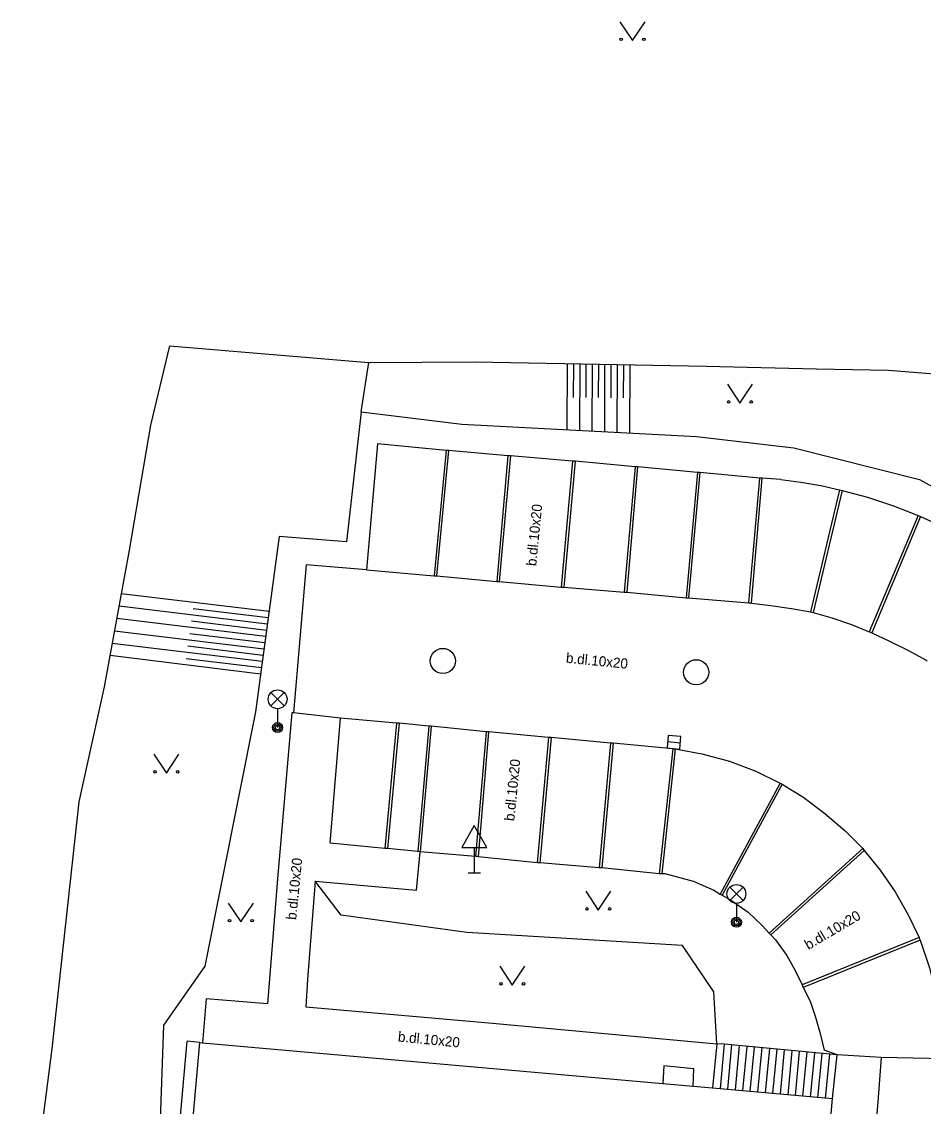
# Model space of a CAD drawing. Extents: x -598233 to -596890, y -1157848 to -1156431.
# Drawn here: x -598000.23 to -597964.39, y -1156908.64 to -1156865.51 of the extents above; entities that cross this region are included whole.
import ezdxf

# ---------------------------------------------------------------- set-up
doc = ezdxf.new("R2010")
doc.units = 0
for name, color, linetype in [('Level 10', 7, 'Continuous'), ('Level 11', 7, 'Continuous'), ('Level 14', 7, 'Continuous'), ('Level 15', 7, 'Continuous'), ('Level 25', 7, 'Continuous'), ('Level 27', 7, 'Continuous'), ('Level 33', 7, 'Continuous'), ('Level 34', 7, 'Continuous'), ('Level 36', 7, 'Continuous'), ('Level 40', 7, 'Continuous'), ('Level 5', 7, 'Continuous')]:
    doc.layers.add(name, color=color, linetype=linetype)

msp = doc.modelspace()

# ---------------------------------------------------------------- linework, layer by layer
at = {"layer": 'Level 10'}
for points in [[(-597970.06, -1156883.72), (-597970.79, -1156883.66), (-597970.84, -1156883.66), (-597970.89, -1156883.66), (-597973.27, -1156883.44), (-597973.32, -1156883.44), (-597973.37, -1156883.44), (-597975.75, -1156883.21), (-597975.8, -1156883.21), (-597975.85, -1156883.21), (-597978.23, -1156882.99), (-597978.28, -1156882.99), (-597978.33, -1156882.99), (-597980.8, -1156882.77), (-597980.85, -1156882.77), (-597980.9, -1156882.77), (-597983.26, -1156882.56), (-597983.31, -1156882.56), (-597983.36, -1156882.56), (-597986.09, -1156882.3), (-597986.53, -1156887.31), (-597988.92, -1156887.11), (-597989.43, -1156892.99)], [(-597970.06, -1156883.72), (-597969.26, -1156883.82), (-597968.46, -1156883.96), (-597967.72, -1156884.13), (-597967.67, -1156884.14)], [(-597967.67, -1156884.14), (-597967.62, -1156884.15), (-597966.61, -1156884.42), (-597965.57, -1156884.76), (-597964.6, -1156885.14), (-597964.55, -1156885.16)], [(-597964.55, -1156885.16), (-597964.5, -1156885.18), (-597963.53, -1156885.62), (-597962.54, -1156886.14), (-597961.61, -1156886.68), (-597961.57, -1156886.7)], [(-597987.97, -1156898.18), (-597987.56, -1156893.2)], [(-597985.74, -1156898.39), (-597985.79, -1156898.39), (-597987.97, -1156898.18)], [(-597984.39, -1156898.52), (-597984.49, -1156898.51), (-597985.69, -1156898.39), (-597985.74, -1156898.39)], [(-597982.14, -1156898.71), (-597982.19, -1156898.71), (-597984.39, -1156898.52)], [(-597979.69, -1156898.96), (-597979.74, -1156898.96), (-597982.09, -1156898.72), (-597982.14, -1156898.71)], [(-597977.22, -1156899.16), (-597977.27, -1156899.16), (-597979.64, -1156898.96), (-597979.69, -1156898.96)], [(-597974.84, -1156899.39), (-597974.89, -1156899.39), (-597977.17, -1156899.16), (-597977.22, -1156899.16)], [(-597974.65, -1156899.39), (-597974.79, -1156899.39), (-597974.84, -1156899.39)], [(-597973.47, -1156899.72), (-597974.65, -1156899.39)], [(-597973.47, -1156899.72), (-597972.72, -1156900.05), (-597972.46, -1156900.2), (-597972.38, -1156900.25), (-597972.01, -1156900.45), (-597971.35, -1156900.92)], [(-597971.35, -1156900.92), (-597970.79, -1156901.45), (-597970.52, -1156901.75), (-597970.45, -1156901.82), (-597970.27, -1156902.02), (-597969.81, -1156902.64)], [(-597969.81, -1156902.64), (-597969.49, -1156903.24), (-597969.21, -1156903.81), (-597969.19, -1156903.85), (-597969.16, -1156903.91), (-597968.89, -1156904.46)], [(-597968.89, -1156904.46), (-597968.67, -1156905.1), (-597968.49, -1156905.75), (-597968.33, -1156906.41)], [(-597967.82, -1156906.59), (-597968.33, -1156906.41)], [(-597963.52, -1156906.75), (-597966.06, -1156906.7), (-597967.82, -1156906.59)]]:
    msp.add_lwpolyline(points, dxfattribs=at)
at = {"layer": 'Level 11'}
for points in [[(-597983.36, -1156882.56), (-597983.84, -1156887.55)], [(-597983.26, -1156882.56), (-597983.74, -1156887.55)], [(-597980.9, -1156882.77), (-597981.35, -1156887.77)], [(-597980.8, -1156882.77), (-597981.25, -1156887.77)], [(-597978.33, -1156882.99), (-597978.78, -1156887.99)], [(-597978.23, -1156882.99), (-597978.68, -1156887.99)], [(-597975.85, -1156883.21), (-597976.28, -1156888.2)], [(-597975.75, -1156883.21), (-597976.18, -1156888.2)], [(-597973.37, -1156883.44), (-597973.82, -1156888.42)], [(-597973.27, -1156883.44), (-597973.72, -1156888.42)], [(-597971.32, -1156888.62), (-597970.89, -1156883.66)], [(-597971.22, -1156888.63), (-597970.79, -1156883.66)], [(-597967.72, -1156884.13), (-597968.87, -1156888.98)], [(-597967.62, -1156884.15), (-597968.77, -1156889)], [(-597964.6, -1156885.14), (-597966.54, -1156889.77)], [(-597964.5, -1156885.18), (-597966.44, -1156889.81)], [(-597986.53, -1156887.31), (-597983.84, -1156887.55), (-597983.79, -1156887.55), (-597983.74, -1156887.55), (-597981.35, -1156887.77), (-597981.3, -1156887.77), (-597981.25, -1156887.77), (-597978.78, -1156887.99), (-597978.73, -1156887.99), (-597978.68, -1156887.99), (-597976.28, -1156888.2), (-597976.23, -1156888.2), (-597976.18, -1156888.2), (-597973.82, -1156888.42), (-597973.77, -1156888.42), (-597973.72, -1156888.42), (-597971.32, -1156888.62), (-597971.27, -1156888.62)], [(-597971.27, -1156888.62), (-597971.22, -1156888.63), (-597970.45, -1156888.72), (-597969.63, -1156888.85), (-597968.87, -1156888.98), (-597968.82, -1156888.99)], [(-597968.82, -1156888.99), (-597968.77, -1156889), (-597968.03, -1156889.22), (-597967.25, -1156889.48), (-597966.54, -1156889.77), (-597966.49, -1156889.79)], [(-597966.49, -1156889.79), (-597966.44, -1156889.81), (-597965.73, -1156890.15), (-597964.98, -1156890.52), (-597964.28, -1156890.9), (-597964.24, -1156890.92)], [(-597989.43, -1156892.99), (-597989.49, -1156893), (-597990.06, -1156899.6), (-597990.46, -1156904.56), (-597992.9, -1156904.36), (-597993.05, -1156906.11)], [(-597974.3, -1156894.42), (-597974.35, -1156894.42), (-597976.72, -1156894.2), (-597976.77, -1156894.2), (-597976.82, -1156894.2), (-597979.19, -1156893.97), (-597979.24, -1156893.97), (-597979.29, -1156893.97), (-597981.67, -1156893.75), (-597981.72, -1156893.75), (-597981.77, -1156893.75), (-597983.95, -1156893.53), (-597984, -1156893.53), (-597984.05, -1156893.53), (-597985.23, -1156893.41), (-597985.28, -1156893.41), (-597985.33, -1156893.41), (-597987.56, -1156893.2), (-597989.43, -1156892.99)], [(-597985.33, -1156893.41), (-597985.79, -1156898.39)], [(-597985.23, -1156893.41), (-597985.69, -1156898.39)], [(-597984.05, -1156893.53), (-597984.49, -1156898.51)], [(-597983.95, -1156893.53), (-597984.39, -1156898.52)], [(-597981.77, -1156893.75), (-597982.19, -1156898.71)], [(-597981.67, -1156893.75), (-597982.09, -1156898.72)], [(-597979.29, -1156893.97), (-597979.74, -1156898.96)], [(-597979.19, -1156893.97), (-597979.64, -1156898.96)], [(-597976.82, -1156894.2), (-597977.27, -1156899.16)], [(-597976.72, -1156894.2), (-597977.17, -1156899.16)], [(-597974.35, -1156894.42), (-597974.89, -1156899.39)], [(-597974.25, -1156894.43), (-597974.79, -1156899.39)], [(-597974.3, -1156894.42), (-597974.25, -1156894.43), (-597973.19, -1156894.62), (-597972.1, -1156894.92), (-597971.05, -1156895.31), (-597970.08, -1156895.79), (-597970.04, -1156895.81)], [(-597970.08, -1156895.79), (-597972.46, -1156900.2)], [(-597970.04, -1156895.81), (-597970, -1156895.83), (-597969.14, -1156896.36), (-597968.3, -1156896.99), (-597967.5, -1156897.68), (-597966.8, -1156898.39), (-597966.77, -1156898.43)], [(-597970, -1156895.83), (-597972.38, -1156900.25)], [(-597966.8, -1156898.39), (-597970.52, -1156901.75)], [(-597984.54, -1156900.04), (-597984.39, -1156898.52)], [(-597966.74, -1156898.47), (-597970.45, -1156901.82)], [(-597966.77, -1156898.43), (-597966.74, -1156898.47), (-597966.11, -1156899.25), (-597965.51, -1156900.11), (-597964.99, -1156901.03), (-597964.56, -1156901.93), (-597964.54, -1156901.98)], [(-597988.56, -1156899.69), (-597988.87, -1156903.6)], [(-597988.56, -1156899.69), (-597984.54, -1156900.04)], [(-597964.56, -1156901.93), (-597969.21, -1156903.81)], [(-597964.52, -1156902.03), (-597969.16, -1156903.91)], [(-597964.54, -1156901.98), (-597964.52, -1156902.03), (-597964.15, -1156903.14), (-597963.85, -1156904.33), (-597963.64, -1156905.53), (-597963.52, -1156906.75)], [(-597988.87, -1156903.6), (-597988.94, -1156904.69)], [(-597988.94, -1156904.69), (-597983.78, -1156905.14)], [(-597983.78, -1156905.14), (-597981.52, -1156905.34)], [(-597981.52, -1156905.34), (-597972.6, -1156906.15)], [(-597995.24, -1156923.9), (-597993.66, -1156906.05)], [(-597993.15, -1156906.1), (-597993.66, -1156906.05)], [(-597972.6, -1156906.15), (-597972.77, -1156907.91)], [(-597972.31, -1156906.17), (-597972.6, -1156906.15)], [(-597972.3, -1156906.17), (-597972.47, -1156907.93)], [(-597967.82, -1156906.59), (-597972.31, -1156906.17)], [(-597972.01, -1156906.2), (-597972.17, -1156907.96)], [(-597971.71, -1156906.23), (-597971.87, -1156907.99)], [(-597971.41, -1156906.26), (-597971.58, -1156908.01)], [(-597971.11, -1156906.29), (-597971.28, -1156908.04)], [(-597970.81, -1156906.31), (-597970.98, -1156908.07)], [(-597970.51, -1156906.34), (-597970.68, -1156908.1)], [(-597970.21, -1156906.37), (-597970.38, -1156908.13)], [(-597969.92, -1156906.4), (-597970.08, -1156908.16)], [(-597969.62, -1156906.43), (-597969.78, -1156908.18)], [(-597969.32, -1156906.46), (-597969.48, -1156908.21)], [(-597969.02, -1156906.48), (-597969.19, -1156908.24)], [(-597968.72, -1156906.51), (-597968.89, -1156908.27)], [(-597968.42, -1156906.54), (-597968.59, -1156908.3)], [(-597968.12, -1156906.57), (-597968.29, -1156908.33)], [(-597968, -1156908.33), (-597967.82, -1156906.59)], [(-597966.06, -1156906.7), (-597966.2, -1156908.47)], [(-597966.2, -1156908.47), (-597966.55, -1156912.52)]]:
    msp.add_lwpolyline(points, dxfattribs=at)
at = {"layer": 'Level 14'}
for points in [[(-597994.36, -1156878.4), (-597995.11, -1156881.55)], [(-597994.36, -1156878.4), (-597986.43, -1156879.06), (-597982.2, -1156879.04), (-597973.02, -1156879.21), (-597968.63, -1156879.31), (-597965.77, -1156879.37), (-597963.29, -1156879.57), (-597960.67, -1156880.27), (-597957.79, -1156881.35), (-597954.02, -1156883.03), (-597950.54, -1156885.46), (-597949.3, -1156888.18), (-597948.87, -1156890.88), (-597947.51, -1156896.41), (-597947.28, -1156899.75), (-597947.23, -1156904)], [(-597986.74, -1156881.03), (-597986.43, -1156879.06)], [(-597986.74, -1156881.03), (-597987.32, -1156886.19)], [(-597986.74, -1156881.03), (-597982.74, -1156881.52), (-597973.41, -1156882), (-597969.54, -1156882.46), (-597964.54, -1156883.71), (-597962.03, -1156885.09), (-597958.89, -1156886.84), (-597956.73, -1156888.67), (-597956.22, -1156888.79), (-597954.06, -1156891.32), (-597951.77, -1156894.98), (-597950.79, -1156898.51), (-597950.25, -1156902.48), (-597950.14, -1156905.8), (-597950.47, -1156911.42), (-597950.16, -1156915.1)], [(-597995.11, -1156881.55), (-597995.96, -1156886.53)], [(-597990, -1156885.98), (-597990.94, -1156892.96)], [(-597987.32, -1156886.19), (-597990, -1156885.98)], [(-597995.96, -1156886.53), (-597996.95, -1156891.96)], [(-597996.95, -1156891.96), (-597997.96, -1156896.53)], [(-597990.94, -1156892.96), (-597992.95, -1156903.07)], [(-597997.96, -1156896.53), (-597999.04, -1156906.35)], [(-597972.6, -1156906.15), (-597972.72, -1156904.09), (-597973.96, -1156902.24), (-597982.53, -1156901.73), (-597987.53, -1156901.04), (-597988.56, -1156899.69)], [(-597992.95, -1156903.07), (-597994.6, -1156905.41)], [(-597994.6, -1156905.41), (-597995.24, -1156923.9)], [(-597999.04, -1156906.35), (-598001.6, -1156926.23)]]:
    msp.add_lwpolyline(points, dxfattribs=at)
at = {"layer": 'Level 15'}
for points in [[(-597978.55, -1156879.11), (-597978.56, -1156881.74)], [(-597978.3, -1156879.11), (-597978.31, -1156880.45)], [(-597978.05, -1156879.12), (-597978.06, -1156881.76)], [(-597977.8, -1156879.12), (-597977.81, -1156880.45)], [(-597977.55, -1156879.13), (-597977.57, -1156881.79)], [(-597977.3, -1156879.13), (-597977.31, -1156880.46)], [(-597977.06, -1156879.14), (-597977.07, -1156881.81)], [(-597976.81, -1156879.14), (-597976.81, -1156880.47)], [(-597976.56, -1156879.14), (-597976.57, -1156881.84)], [(-597976.31, -1156879.15), (-597976.32, -1156880.47)], [(-597976.06, -1156879.15), (-597976.07, -1156881.86)], [(-597990.4, -1156888.97), (-597996.28, -1156888.26)], [(-597990.47, -1156889.47), (-597996.36, -1156888.75)], [(-597990.44, -1156889.22), (-597993.41, -1156888.86)], [(-597990.54, -1156889.96), (-597996.45, -1156889.24)], [(-597990.5, -1156889.72), (-597993.48, -1156889.35)], [(-597990.6, -1156890.46), (-597996.54, -1156889.74)], [(-597990.57, -1156890.21), (-597993.55, -1156889.85)], [(-597990.67, -1156890.95), (-597996.63, -1156890.23)], [(-597990.64, -1156890.71), (-597993.63, -1156890.34)], [(-597990.74, -1156891.45), (-597996.72, -1156890.72)], [(-597990.7, -1156891.2), (-597993.7, -1156890.84)]]:
    msp.add_lwpolyline(points, dxfattribs=at)
at = {"layer": 'Level 25'}
for points in [[(-597974.71, -1156907.03), (-597974.74, -1156907.73)], [(-597973.51, -1156907.15), (-597974.71, -1156907.03)], [(-597973.54, -1156907.84), (-597973.51, -1156907.15)]]:
    msp.add_lwpolyline(points, dxfattribs=at)
at = {"layer": 'Level 27'}
msp.add_line((-597974.549, -1156894.1372), (-597974.051, -1156894.1828), dxfattribs=at)
msp.add_lwpolyline([(-597974.5717, -1156894.3862), (-597974.0738, -1156894.4317), (-597974.0283, -1156893.9338), (-597974.5262, -1156893.8883)], close=True, dxfattribs=at)
for centre in [(-597983.49, -1156890.93), (-597973.42, -1156891.38)]:
    msp.add_circle(centre, 0.5, dxfattribs=at)
at = {"layer": 'Level 33'}
for p, q in [((-597990.325, -1156892.72), (-597989.795, -1156892.19)), ((-597990.325, -1156892.19), (-597989.795, -1156892.72)), ((-597990.06, -1156892.83), (-597990.06, -1156893.58)), ((-597972.085, -1156900.46), (-597971.555, -1156899.93)), ((-597972.085, -1156899.93), (-597971.555, -1156900.46)), ((-597971.82, -1156900.57), (-597971.82, -1156901.32))]:
    msp.add_line(p, q, dxfattribs=at)
for centre, radius in [((-597990.06, -1156892.455), 0.375), ((-597990.06, -1156893.58), 0.2), ((-597990.06, -1156893.58), 0.1445), ((-597990.06, -1156893.58), 0.0876), ((-597971.82, -1156900.195), 0.375), ((-597971.82, -1156901.32), 0.2), ((-597971.82, -1156901.32), 0.1445), ((-597971.82, -1156901.32), 0.0876)]:
    msp.add_circle(centre, radius, dxfattribs=at)
at = {"layer": 'Level 34'}
for p, q in [((-597982.24, -1156898.342), (-597982.24, -1156899.36)), ((-597982.49, -1156899.36), (-597981.99, -1156899.36))]:
    msp.add_line(p, q, dxfattribs=at)
msp.add_lwpolyline([(-597982.74, -1156898.342), (-597981.74, -1156898.342), (-597982.24, -1156897.476)], close=True, dxfattribs=at)
at = {"layer": 'Level 36'}
for points in [[(-597976.45, -1156865.51), (-597975.95, -1156866.26), (-597975.45, -1156865.51)], [(-597972.18, -1156879.93), (-597971.68, -1156880.68), (-597971.18, -1156879.93)], [(-597994.98, -1156894.64), (-597994.48, -1156895.39), (-597993.98, -1156894.64)], [(-597977.81, -1156900.09), (-597977.31, -1156900.84), (-597976.81, -1156900.09)], [(-597992.02, -1156900.56), (-597991.52, -1156901.31), (-597991.02, -1156900.56)], [(-597981.23, -1156903.07), (-597980.73, -1156903.82), (-597980.23, -1156903.07)]]:
    msp.add_lwpolyline(points, dxfattribs=at)
for centre in [(-597976.4002, -1156866.2098), (-597975.5008, -1156866.2098), (-597972.1302, -1156880.6298), (-597971.2308, -1156880.6298), (-597994.9302, -1156895.3398), (-597994.0308, -1156895.3398), (-597977.7602, -1156900.7898), (-597976.8608, -1156900.7898), (-597991.9702, -1156901.2598), (-597991.0708, -1156901.2598), (-597981.1802, -1156903.7698), (-597980.2808, -1156903.7698)]:
    msp.add_circle(centre, 0.05, dxfattribs=at)
at = {"layer": 'Level 5'}
for points in [[(-597994.69, -1156923.41), (-597993.15, -1156906.1)], [(-597993.15, -1156906.1), (-597993.05, -1156906.11), (-597974.74, -1156907.73), (-597973.54, -1156907.84), (-597972.77, -1156907.91), (-597968, -1156908.33)], [(-597968.54, -1156914.52), (-597968, -1156908.33)]]:
    msp.add_lwpolyline(points, dxfattribs=at)

# ---------------------------------------------------------------- texts
at = {"layer": 'Level 40'}
for rotation, p in [(84.36317, (-597979.78, -1156887.17)), (354.36317, (-597978.61, -1156891)), (84.36317, (-597980.65, -1156897.31)), (84.36317, (-597989.32, -1156901.24)), (30.69204, (-597968.96, -1156902.43)), (354.36317, (-597985.29, -1156906.06))]:
    msp.add_text('b.dl.10x20', height=0.4, rotation=rotation, dxfattribs=at).set_placement(p)

doc.saveas('drawing.dxf')
